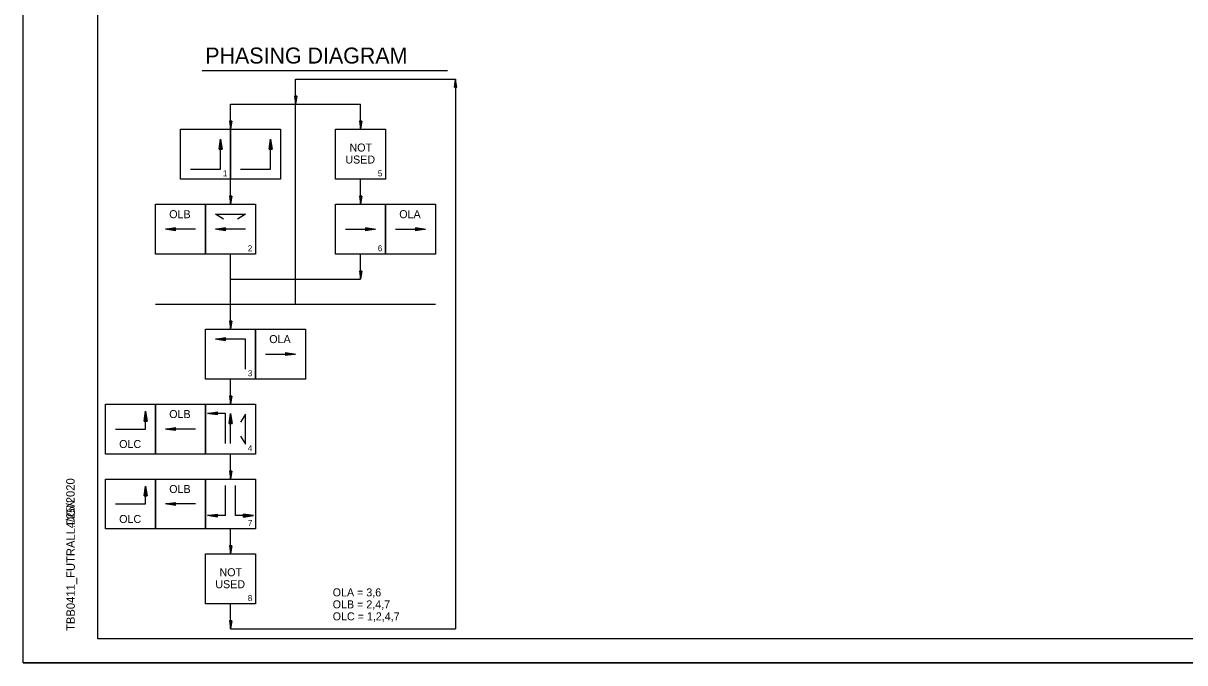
# Model space of a CAD drawing. Extents: x 662183 to 663183, y 642099 to 642739.
# Drawn here: x 662183 to 662763, y 642099 to 642419 of the extents above; entities that cross this region are included whole.
import ezdxf

# ---------------------------------------------------------------- set-up
doc = ezdxf.new("R2010")
doc.units = 0
for name, color, linetype in [('Default', 7, 'Continuous'), ('R_Border', 7, 'Continuous'), ('R_No Plot', 7, 'Continuous'), ('T_Drafting', 7, 'Continuous'), ('T_Notes', 7, 'Continuous')]:
    doc.layers.add(name, color=color, linetype=linetype)

msp = doc.modelspace()

# ---------------------------------------------------------------- linework, layer by layer
at = {"layer": 'Default'}
for p, q in [((662272.06, 642395.65), (662394.71, 642395.65)), ((662398.19, 642387.24), (662398.79, 642391.24)), ((662398.29, 642387.24), (662398.79, 642390.57)), ((662398.39, 642387.24), (662398.79, 642389.89)), ((662398.49, 642387.24), (662398.79, 642389.22)), ((662399.39, 642387.24), (662398.79, 642391.24)), ((662399.29, 642387.24), (662398.79, 642390.57)), ((662399.19, 642387.24), (662398.79, 642389.89)), ((662399.09, 642387.24), (662398.79, 642389.22)), ((662398.19, 642387.24), (662399.39, 642387.24)), ((662398.59, 642387.24), (662398.79, 642388.54)), ((662398.69, 642387.24), (662398.79, 642387.87)), ((662398.98, 642387.24), (662398.79, 642388.54)), ((662398.88, 642387.24), (662398.79, 642387.87)), ((662318.19, 642382.74), (662318.79, 642378.74)), ((662319.39, 642382.74), (662318.19, 642382.74)), ((662318.29, 642382.74), (662318.79, 642379.41)), ((662318.39, 642382.74), (662318.79, 642380.1)), ((662318.49, 642382.74), (662318.79, 642380.76)), ((662318.59, 642382.74), (662318.79, 642381.44)), ((662318.69, 642382.74), (662318.79, 642382.11)), ((662319.39, 642382.74), (662318.79, 642378.74)), ((662318.98, 642382.74), (662318.79, 642381.44)), ((662319.19, 642382.74), (662318.79, 642380.1)), ((662319.29, 642382.74), (662318.79, 642379.41)), ((662319.09, 642382.74), (662318.79, 642380.76)), ((662318.88, 642382.74), (662318.79, 642382.11)), ((662285.69, 642370.24), (662286.29, 642366.24)), ((662286.89, 642370.24), (662285.69, 642370.24)), ((662285.79, 642370.24), (662286.29, 642366.91)), ((662285.89, 642370.24), (662286.29, 642367.6)), ((662285.99, 642370.24), (662286.29, 642368.26)), ((662286.09, 642370.24), (662286.29, 642368.94)), ((662286.19, 642370.24), (662286.29, 642369.61)), ((662286.89, 642370.24), (662286.29, 642366.24)), ((662286.48, 642370.24), (662286.29, 642368.94)), ((662286.69, 642370.24), (662286.29, 642367.6)), ((662286.79, 642370.24), (662286.29, 642366.91)), ((662286.59, 642370.24), (662286.29, 642368.26)), ((662286.38, 642370.24), (662286.29, 642369.61)), ((662350.69, 642370.24), (662351.29, 642366.24)), ((662351.89, 642370.24), (662350.69, 642370.24)), ((662350.79, 642370.24), (662351.29, 642366.91)), ((662350.89, 642370.24), (662351.29, 642367.6)), ((662350.99, 642370.24), (662351.29, 642368.26)), ((662351.09, 642370.24), (662351.29, 642368.94)), ((662351.19, 642370.24), (662351.29, 642369.61)), ((662351.89, 642370.24), (662351.29, 642366.24)), ((662351.48, 642370.24), (662351.29, 642368.94)), ((662351.69, 642370.24), (662351.29, 642367.6)), ((662351.79, 642370.24), (662351.29, 642366.91)), ((662351.59, 642370.24), (662351.29, 642368.26)), ((662351.38, 642370.24), (662351.29, 642369.61)), ((662285.69, 642332.74), (662286.29, 642328.74)), ((662286.89, 642332.74), (662285.69, 642332.74)), ((662285.79, 642332.74), (662286.29, 642329.41)), ((662285.89, 642332.74), (662286.29, 642330.1)), ((662285.99, 642332.74), (662286.29, 642330.76)), ((662286.09, 642332.74), (662286.29, 642331.44)), ((662286.19, 642332.74), (662286.29, 642332.11)), ((662286.89, 642332.74), (662286.29, 642328.74)), ((662286.48, 642332.74), (662286.29, 642331.44)), ((662286.69, 642332.74), (662286.29, 642330.1)), ((662286.79, 642332.74), (662286.29, 642329.41)), ((662286.59, 642332.74), (662286.29, 642330.76)), ((662286.38, 642332.74), (662286.29, 642332.11)), ((662350.69, 642332.74), (662351.29, 642328.74)), ((662351.89, 642332.74), (662350.69, 642332.74)), ((662350.79, 642332.74), (662351.29, 642329.41)), ((662350.89, 642332.74), (662351.29, 642330.1)), ((662350.99, 642332.74), (662351.29, 642330.76)), ((662351.09, 642332.74), (662351.29, 642331.44)), ((662351.19, 642332.74), (662351.29, 642332.11)), ((662351.89, 642332.74), (662351.29, 642328.74)), ((662351.48, 642332.74), (662351.29, 642331.44)), ((662351.69, 642332.74), (662351.29, 642330.1)), ((662351.79, 642332.74), (662351.29, 642329.41)), ((662351.59, 642332.74), (662351.29, 642330.76)), ((662351.38, 642332.74), (662351.29, 642332.11)), ((662350.69, 642295.24), (662351.29, 642291.24)), ((662351.89, 642295.24), (662350.69, 642295.24)), ((662350.79, 642295.24), (662351.29, 642291.91)), ((662350.89, 642295.24), (662351.29, 642292.6)), ((662350.99, 642295.24), (662351.29, 642293.26)), ((662351.09, 642295.24), (662351.29, 642293.94)), ((662351.19, 642295.24), (662351.29, 642294.61)), ((662351.89, 642295.24), (662351.29, 642291.24)), ((662351.48, 642295.24), (662351.29, 642293.94)), ((662351.69, 642295.24), (662351.29, 642292.6)), ((662351.79, 642295.24), (662351.29, 642291.91)), ((662351.59, 642295.24), (662351.29, 642293.26)), ((662351.38, 642295.24), (662351.29, 642294.61)), ((662285.69, 642270.24), (662286.29, 642266.24)), ((662286.89, 642270.24), (662285.69, 642270.24)), ((662285.79, 642270.24), (662286.29, 642266.91)), ((662285.89, 642270.24), (662286.29, 642267.6)), ((662285.99, 642270.24), (662286.29, 642268.26)), ((662286.09, 642270.24), (662286.29, 642268.94)), ((662286.19, 642270.24), (662286.29, 642269.61)), ((662286.89, 642270.24), (662286.29, 642266.24)), ((662286.48, 642270.24), (662286.29, 642268.94)), ((662286.69, 642270.24), (662286.29, 642267.6)), ((662286.79, 642270.24), (662286.29, 642266.91)), ((662286.59, 642270.24), (662286.29, 642268.26)), ((662286.38, 642270.24), (662286.29, 642269.61)), ((662285.69, 642232.74), (662286.29, 642228.74)), ((662286.89, 642232.74), (662285.69, 642232.74)), ((662285.79, 642232.74), (662286.29, 642229.41)), ((662285.89, 642232.74), (662286.29, 642230.1)), ((662285.99, 642232.74), (662286.29, 642230.76)), ((662286.09, 642232.74), (662286.29, 642231.44)), ((662286.19, 642232.74), (662286.29, 642232.11)), ((662286.89, 642232.74), (662286.29, 642228.74)), ((662286.48, 642232.74), (662286.29, 642231.44)), ((662286.69, 642232.74), (662286.29, 642230.1)), ((662286.79, 642232.74), (662286.29, 642229.41)), ((662286.59, 642232.74), (662286.29, 642230.76)), ((662286.38, 642232.74), (662286.29, 642232.11)), ((662285.69, 642195.24), (662286.29, 642191.24)), ((662286.89, 642195.24), (662285.69, 642195.24)), ((662285.79, 642195.24), (662286.29, 642191.91)), ((662285.89, 642195.24), (662286.29, 642192.6)), ((662285.99, 642195.24), (662286.29, 642193.26)), ((662286.09, 642195.24), (662286.29, 642193.94)), ((662286.19, 642195.24), (662286.29, 642194.61)), ((662286.89, 642195.24), (662286.29, 642191.24)), ((662286.48, 642195.24), (662286.29, 642193.94)), ((662286.69, 642195.24), (662286.29, 642192.6)), ((662286.79, 642195.24), (662286.29, 642191.91)), ((662286.59, 642195.24), (662286.29, 642193.26)), ((662286.38, 642195.24), (662286.29, 642194.61)), ((662285.69, 642157.74), (662286.29, 642153.74)), ((662286.89, 642157.74), (662285.69, 642157.74)), ((662285.79, 642157.74), (662286.29, 642154.41)), ((662285.89, 642157.74), (662286.29, 642155.1)), ((662285.99, 642157.74), (662286.29, 642155.76)), ((662286.09, 642157.74), (662286.29, 642156.44)), ((662286.19, 642157.74), (662286.29, 642157.11)), ((662286.89, 642157.74), (662286.29, 642153.74)), ((662286.48, 642157.74), (662286.29, 642156.44)), ((662286.69, 642157.74), (662286.29, 642155.1)), ((662286.79, 642157.74), (662286.29, 642154.41)), ((662286.59, 642157.74), (662286.29, 642155.76)), ((662286.38, 642157.74), (662286.29, 642157.11)), ((662285.69, 642120.24), (662286.29, 642116.24)), ((662286.89, 642120.24), (662285.69, 642120.24)), ((662285.79, 642120.24), (662286.29, 642116.91)), ((662285.89, 642120.24), (662286.29, 642117.6)), ((662285.99, 642120.24), (662286.29, 642118.26)), ((662286.09, 642120.24), (662286.29, 642118.94)), ((662286.19, 642120.24), (662286.29, 642119.61)), ((662286.89, 642120.24), (662286.29, 642116.24)), ((662286.48, 642120.24), (662286.29, 642118.94)), ((662286.69, 642120.24), (662286.29, 642117.6)), ((662286.79, 642120.24), (662286.29, 642116.91)), ((662286.59, 642120.24), (662286.29, 642118.26)), ((662286.38, 642120.24), (662286.29, 642119.61))]:
    msp.add_line(p, q, dxfattribs=at)
at = {"layer": 'R_Border'}
for p, q in [((662219.86, 642111.24), (662219.86, 642727.62)), ((662219.86, 642111.24), (662219.86, 642111.24)), ((663168.4, 642111.24), (662219.86, 642111.24))]:
    msp.add_line(p, q, dxfattribs=at)
at = {"layer": 'R_No Plot'}
msp.add_line((662182.66, 642099.3), (663182.66, 642099.3), dxfattribs=at)
msp.add_lwpolyline([(662182.64, 642739.3), (663182.66, 642739.3), (663182.66, 642099.29), (662182.64, 642099.29)], close=True, dxfattribs=at)
at = {"layer": 'T_Drafting'}
for p, q in [((662318.79, 642278.74), (662318.79, 642391.24)), ((662318.79, 642391.24), (662398.79, 642391.24)), ((662398.79, 642391.24), (662398.79, 642116.24)), ((662286.29, 642366.24), (662286.29, 642378.74)), ((662286.29, 642378.74), (662351.29, 642378.74)), ((662351.29, 642366.24), (662351.29, 642378.74)), ((662280.54, 642356.24), (662281.29, 642361.24)), ((662281.29, 642360.41), (662280.66, 642356.24)), ((662280.79, 642356.24), (662281.29, 642359.55)), ((662281.29, 642346.24), (662281.29, 642361.24)), ((662281.29, 642361.24), (662282.04, 642356.24)), ((662281.91, 642356.24), (662281.29, 642360.41)), ((662281.29, 642359.55), (662281.79, 642356.24)), ((662305.54, 642356.24), (662306.29, 642361.24)), ((662306.29, 642360.41), (662305.66, 642356.24)), ((662305.79, 642356.24), (662306.29, 642359.55)), ((662306.29, 642346.24), (662306.29, 642361.24)), ((662306.29, 642361.24), (662307.04, 642356.24)), ((662306.91, 642356.24), (662306.29, 642360.41)), ((662306.29, 642359.55), (662306.79, 642356.24)), ((662280.54, 642356.24), (662282.04, 642356.24)), ((662281.29, 642358.71), (662280.92, 642356.24)), ((662281.05, 642356.24), (662281.29, 642357.87)), ((662281.29, 642357.03), (662281.17, 642356.24)), ((662281.66, 642356.24), (662281.29, 642358.71)), ((662281.29, 642357.87), (662281.53, 642356.24)), ((662281.41, 642356.24), (662281.29, 642357.03)), ((662305.54, 642356.24), (662307.04, 642356.24)), ((662306.29, 642358.71), (662305.92, 642356.24)), ((662306.05, 642356.24), (662306.29, 642357.87)), ((662306.29, 642357.03), (662306.17, 642356.24)), ((662306.66, 642356.24), (662306.29, 642358.71)), ((662306.29, 642357.87), (662306.53, 642356.24)), ((662306.41, 642356.24), (662306.29, 642357.03)), ((662266.29, 642346.24), (662281.29, 642346.24)), ((662291.29, 642346.24), (662306.29, 642346.24)), ((662286.29, 642328.74), (662286.29, 642341.24)), ((662351.29, 642328.74), (662351.29, 642341.24)), ((662253.79, 642316.24), (662258.79, 642316.99)), ((662268.79, 642316.24), (662253.79, 642316.24)), ((662258.79, 642315.49), (662253.79, 642316.24)), ((662258.79, 642316.87), (662254.62, 642316.24)), ((662254.62, 642316.24), (662258.79, 642315.62)), ((662255.48, 642316.24), (662258.79, 642316.74)), ((662258.79, 642315.74), (662255.48, 642316.24)), ((662258.79, 642316.61), (662256.32, 642316.24)), ((662256.32, 642316.24), (662258.79, 642315.87)), ((662257.16, 642316.24), (662258.79, 642316.49)), ((662258.79, 642316), (662257.16, 642316.24)), ((662258.79, 642316.36), (662258, 642316.24)), ((662258, 642316.24), (662258.79, 642316.12)), ((662258.79, 642315.49), (662258.79, 642316.99)), ((662278.79, 642316.24), (662283.79, 642316.99)), ((662293.79, 642316.24), (662278.79, 642316.24)), ((662283.79, 642315.49), (662278.79, 642316.24)), ((662283.79, 642316.87), (662279.62, 642316.24)), ((662279.62, 642316.24), (662283.79, 642315.62)), ((662280.48, 642316.24), (662283.79, 642316.74)), ((662283.79, 642315.74), (662280.48, 642316.24)), ((662283.79, 642316.61), (662281.32, 642316.24)), ((662281.32, 642316.24), (662283.79, 642315.87)), ((662282.16, 642316.24), (662283.79, 642316.49)), ((662283.79, 642316), (662282.16, 642316.24)), ((662283.79, 642316.36), (662283, 642316.24)), ((662283, 642316.24), (662283.79, 642316.12)), ((662283.79, 642315.49), (662283.79, 642316.99)), ((662343.79, 642316.24), (662358.79, 642316.24)), ((662353.79, 642316.99), (662358.79, 642316.24)), ((662353.79, 642316.99), (662353.79, 642315.49)), ((662357.95, 642316.24), (662353.79, 642316.87)), ((662353.79, 642316.74), (662357.09, 642316.24)), ((662356.26, 642316.24), (662353.79, 642316.61)), ((662353.79, 642316.48), (662355.41, 642316.24)), ((662354.58, 642316.24), (662353.79, 642316.36)), ((662358.79, 642316.24), (662353.79, 642315.49)), ((662353.79, 642315.62), (662357.95, 642316.24)), ((662357.09, 642316.24), (662353.79, 642315.74)), ((662353.79, 642315.87), (662356.26, 642316.24)), ((662355.41, 642316.24), (662353.79, 642316)), ((662353.79, 642316.12), (662354.58, 642316.24)), ((662368.79, 642316.24), (662383.79, 642316.24)), ((662378.79, 642316.99), (662383.79, 642316.24)), ((662378.79, 642316.99), (662378.79, 642315.49)), ((662382.95, 642316.24), (662378.79, 642316.87)), ((662378.79, 642316.74), (662382.09, 642316.24)), ((662381.26, 642316.24), (662378.79, 642316.61)), ((662378.79, 642316.48), (662380.41, 642316.24)), ((662379.58, 642316.24), (662378.79, 642316.36)), ((662383.79, 642316.24), (662378.79, 642315.49)), ((662378.79, 642315.62), (662382.95, 642316.24)), ((662382.09, 642316.24), (662378.79, 642315.74)), ((662378.79, 642315.87), (662381.26, 642316.24)), ((662380.41, 642316.24), (662378.79, 642316)), ((662378.79, 642316.12), (662379.58, 642316.24)), ((662286.29, 642266.24), (662286.29, 642303.74)), ((662351.29, 642291.24), (662351.29, 642303.74)), ((662286.29, 642291.24), (662351.29, 642291.24)), ((662248.79, 642278.74), (662388.79, 642278.74)), ((662278.79, 642261.24), (662283.79, 642261.99)), ((662293.79, 642261.24), (662278.79, 642261.24)), ((662283.79, 642260.49), (662278.79, 642261.24)), ((662283.79, 642261.87), (662279.62, 642261.24)), ((662279.62, 642261.24), (662283.79, 642260.62)), ((662280.48, 642261.24), (662283.79, 642261.74)), ((662283.79, 642260.74), (662280.48, 642261.24)), ((662283.79, 642261.61), (662281.32, 642261.24)), ((662281.32, 642261.24), (662283.79, 642260.87)), ((662282.16, 642261.24), (662283.79, 642261.49)), ((662283.79, 642261), (662282.16, 642261.24)), ((662283.79, 642261.36), (662283, 642261.24)), ((662283, 642261.24), (662283.79, 642261.12)), ((662283.79, 642260.49), (662283.79, 642261.99)), ((662293.79, 642246.24), (662293.79, 642261.24)), ((662303.79, 642253.74), (662318.79, 642253.74)), ((662313.79, 642254.49), (662318.79, 642253.74)), ((662313.79, 642254.49), (662313.79, 642252.99)), ((662317.95, 642253.74), (662313.79, 642254.37)), ((662313.79, 642254.24), (662317.09, 642253.74)), ((662316.26, 642253.74), (662313.79, 642254.11)), ((662313.79, 642253.98), (662315.41, 642253.74)), ((662314.58, 642253.74), (662313.79, 642253.86)), ((662318.79, 642253.74), (662313.79, 642252.99)), ((662313.79, 642253.12), (662317.95, 642253.74)), ((662317.09, 642253.74), (662313.79, 642253.24)), ((662313.79, 642253.37), (662316.26, 642253.74)), ((662315.41, 642253.74), (662313.79, 642253.5)), ((662313.79, 642253.62), (662314.58, 642253.74)), ((662286.29, 642228.74), (662286.29, 642241.24)), ((662243.04, 642220.24), (662243.79, 642225.24)), ((662243.04, 642220.24), (662244.54, 642220.24)), ((662243.79, 642224.41), (662243.16, 642220.24)), ((662243.29, 642220.24), (662243.79, 642223.55)), ((662243.79, 642222.71), (662243.42, 642220.24)), ((662243.55, 642220.24), (662243.79, 642221.87)), ((662243.79, 642221.03), (662243.67, 642220.24)), ((662243.79, 642216.24), (662243.79, 642225.24)), ((662243.79, 642225.24), (662244.54, 642220.24)), ((662244.41, 642220.24), (662243.79, 642224.41)), ((662243.79, 642223.55), (662244.29, 642220.24)), ((662244.16, 642220.24), (662243.79, 642222.71)), ((662243.79, 642221.87), (662244.03, 642220.24)), ((662243.91, 642220.24), (662243.79, 642221.03)), ((662274.79, 642224.08), (662279.79, 642224.83)), ((662283.79, 642224.08), (662274.79, 642224.08)), ((662279.79, 642223.33), (662274.79, 642224.08)), ((662279.79, 642224.7), (662275.62, 642224.08)), ((662275.62, 642224.08), (662279.79, 642223.45)), ((662276.48, 642224.08), (662279.79, 642224.57)), ((662279.79, 642223.58), (662276.48, 642224.08)), ((662279.79, 642224.45), (662277.32, 642224.08)), ((662277.32, 642224.08), (662279.79, 642223.7)), ((662278.16, 642224.08), (662279.79, 642224.32)), ((662279.79, 642223.83), (662278.16, 642224.08)), ((662279.79, 642224.19), (662279, 642224.08)), ((662279, 642224.08), (662279.79, 642223.96)), ((662279.79, 642223.33), (662279.79, 642224.83)), ((662283.79, 642209.08), (662283.79, 642224.08)), ((662285.54, 642219.08), (662286.29, 642224.08)), ((662286.29, 642223.24), (662285.66, 642219.08)), ((662285.79, 642219.08), (662286.29, 642222.38)), ((662286.29, 642221.55), (662285.92, 642219.08)), ((662286.05, 642219.08), (662286.29, 642220.7)), ((662286.29, 642209.08), (662286.29, 642224.08)), ((662286.29, 642224.08), (662287.04, 642219.08)), ((662286.91, 642219.08), (662286.29, 642223.24)), ((662286.29, 642222.38), (662286.79, 642219.08)), ((662286.66, 642219.08), (662286.29, 642221.55)), ((662286.29, 642220.7), (662286.53, 642219.08)), ((662228.79, 642216.24), (662243.79, 642216.24)), ((662253.79, 642216.24), (662258.79, 642216.99)), ((662268.79, 642216.24), (662253.79, 642216.24)), ((662258.79, 642215.49), (662253.79, 642216.24)), ((662258.79, 642216.87), (662254.62, 642216.24)), ((662254.62, 642216.24), (662258.79, 642215.62)), ((662255.48, 642216.24), (662258.79, 642216.74)), ((662258.79, 642215.74), (662255.48, 642216.24)), ((662258.79, 642216.61), (662256.32, 642216.24)), ((662256.32, 642216.24), (662258.79, 642215.87)), ((662257.16, 642216.24), (662258.79, 642216.49)), ((662258.79, 642216), (662257.16, 642216.24)), ((662258.79, 642216.36), (662258, 642216.24)), ((662258, 642216.24), (662258.79, 642216.12)), ((662258.79, 642215.49), (662258.79, 642216.99)), ((662285.54, 642219.08), (662287.04, 642219.08)), ((662286.29, 642219.87), (662286.17, 642219.08)), ((662286.41, 642219.08), (662286.29, 642219.87)), ((662286.29, 642191.24), (662286.29, 642203.74)), ((662243.04, 642182.74), (662243.79, 642187.74)), ((662243.79, 642186.91), (662243.16, 642182.74)), ((662243.29, 642182.74), (662243.79, 642186.05)), ((662243.79, 642178.74), (662243.79, 642187.74)), ((662243.79, 642187.74), (662244.54, 642182.74)), ((662244.41, 642182.74), (662243.79, 642186.91)), ((662243.79, 642186.05), (662244.29, 642182.74)), ((662283.79, 642172.91), (662283.79, 642187.91)), ((662288.79, 642172.91), (662288.79, 642187.91)), ((662243.04, 642182.74), (662244.54, 642182.74)), ((662243.79, 642185.21), (662243.42, 642182.74)), ((662243.55, 642182.74), (662243.79, 642184.37)), ((662243.79, 642183.53), (662243.67, 642182.74)), ((662244.16, 642182.74), (662243.79, 642185.21)), ((662243.79, 642184.37), (662244.03, 642182.74)), ((662243.91, 642182.74), (662243.79, 642183.53)), ((662253.79, 642178.74), (662258.79, 642179.49)), ((662258.79, 642177.99), (662258.79, 642179.49)), ((662228.79, 642178.74), (662243.79, 642178.74)), ((662268.79, 642178.74), (662253.79, 642178.74)), ((662258.79, 642177.99), (662253.79, 642178.74)), ((662258.79, 642179.37), (662254.62, 642178.74)), ((662254.62, 642178.74), (662258.79, 642178.12)), ((662255.48, 642178.74), (662258.79, 642179.24)), ((662258.79, 642178.24), (662255.48, 642178.74)), ((662258.79, 642179.11), (662256.32, 642178.74)), ((662256.32, 642178.74), (662258.79, 642178.37)), ((662257.16, 642178.74), (662258.79, 642178.99)), ((662258.79, 642178.5), (662257.16, 642178.74)), ((662258.79, 642178.86), (662258, 642178.74)), ((662258, 642178.74), (662258.79, 642178.62)), ((662274.79, 642172.91), (662279.79, 642173.66)), ((662283.79, 642172.91), (662274.79, 642172.91)), ((662279.79, 642172.16), (662274.79, 642172.91)), ((662279.79, 642173.54), (662275.62, 642172.91)), ((662275.62, 642172.91), (662279.79, 642172.29)), ((662276.48, 642172.91), (662279.79, 642173.41)), ((662279.79, 642172.41), (662276.48, 642172.91)), ((662279.79, 642173.28), (662277.32, 642172.91)), ((662277.32, 642172.91), (662279.79, 642172.54)), ((662278.16, 642172.91), (662279.79, 642173.16)), ((662279.79, 642172.67), (662278.16, 642172.91)), ((662279.79, 642173.03), (662279, 642172.91)), ((662279, 642172.91), (662279.79, 642172.79)), ((662279.79, 642172.16), (662279.79, 642173.66)), ((662297.79, 642172.91), (662288.79, 642172.91)), ((662297.79, 642172.91), (662292.79, 642173.66)), ((662292.79, 642172.16), (662292.79, 642173.66)), ((662292.79, 642173.54), (662296.95, 642172.91)), ((662296.09, 642172.91), (662292.79, 642173.41)), ((662292.79, 642173.28), (662295.26, 642172.91)), ((662294.41, 642172.91), (662292.79, 642173.16)), ((662292.79, 642173.03), (662293.58, 642172.91)), ((662293.58, 642172.91), (662292.79, 642172.79)), ((662292.79, 642172.67), (662294.41, 642172.91)), ((662295.26, 642172.91), (662292.79, 642172.54)), ((662292.79, 642172.41), (662296.09, 642172.91)), ((662296.95, 642172.91), (662292.79, 642172.29)), ((662292.79, 642172.16), (662297.79, 642172.91)), ((662286.29, 642153.74), (662286.29, 642166.24)), ((662286.29, 642116.24), (662286.29, 642128.74)), ((662286.29, 642116.24), (662398.79, 642116.24))]:
    msp.add_line(p, q, dxfattribs=at)
for points in [[(662261.29, 642366.24), (662286.29, 642366.24), (662286.29, 642341.24), (662261.29, 642341.24)], [(662286.29, 642366.24), (662311.29, 642366.24), (662311.29, 642341.24), (662286.29, 642341.24)], [(662338.79, 642366.24), (662363.79, 642366.24), (662363.79, 642341.24), (662338.79, 642341.24)], [(662248.79, 642328.74), (662273.79, 642328.74), (662273.79, 642303.74), (662248.79, 642303.74)], [(662273.79, 642328.74), (662298.79, 642328.74), (662298.79, 642303.74), (662273.79, 642303.74)], [(662338.79, 642328.74), (662363.79, 642328.74), (662363.79, 642303.74), (662338.79, 642303.74)], [(662363.79, 642328.74), (662388.79, 642328.74), (662388.79, 642303.74), (662363.79, 642303.74)], [(662273.79, 642266.24), (662298.79, 642266.24), (662298.79, 642241.24), (662273.79, 642241.24)], [(662298.79, 642266.24), (662323.79, 642266.24), (662323.79, 642241.24), (662298.79, 642241.24)], [(662223.79, 642228.74), (662248.79, 642228.74), (662248.79, 642203.74), (662223.79, 642203.74)], [(662248.79, 642228.74), (662273.79, 642228.74), (662273.79, 642203.74), (662248.79, 642203.74)], [(662273.79, 642228.74), (662298.79, 642228.74), (662298.79, 642203.74), (662273.79, 642203.74)], [(662223.79, 642191.24), (662248.79, 642191.24), (662248.79, 642166.24), (662223.79, 642166.24)], [(662248.79, 642191.24), (662273.79, 642191.24), (662273.79, 642166.24), (662248.79, 642166.24)], [(662273.79, 642191.24), (662298.79, 642191.24), (662298.79, 642166.24), (662273.79, 642166.24)], [(662273.79, 642153.74), (662298.79, 642153.74), (662298.79, 642128.74), (662273.79, 642128.74)]]:
    msp.add_lwpolyline(points, close=True, dxfattribs=at)
for points in [[(662282.79, 642321.24), (662278.79, 642323.74), (662293.79, 642323.74), (662289.79, 642321.24)], [(662291.29, 642212.74), (662293.79, 642208.74), (662293.79, 642223.74), (662291.29, 642219.74)]]:
    msp.add_lwpolyline(points, dxfattribs=at)

# ---------------------------------------------------------------- texts
at = {"layer": 'Default'}
for s, height, p in [('PHASING DIAGRAM', 8, (662273.66, 642399.12)), ('1', 3, (662282.44, 642342.66)), ('2', 3, (662294.94, 642305.16)), ('6', 3, (662359.94, 642305.16)), ('3', 3, (662294.94, 642242.66)), ('4', 3, (662294.94, 642205.16)), ('7', 3, (662294.94, 642167.66))]:
    msp.add_text(s, height=height, dxfattribs=at).set_placement(p)
at = {"layer": 'R_Border'}
for s, p in [('4/25/2020', (662208.34, 642166.63)), ('TBB0411_FUTRALL.DGN', (662208.44, 642115.21))]:
    msp.add_text(s, height=4.2, rotation=90, dxfattribs=at).set_placement(p)
at = {"layer": 'T_Drafting'}
for s, height, p in [('NOT', 4, (662345.76, 642355.09)), ('USED', 4, (662343.69, 642349.09)), ('5', 3, (662359.94, 642342.66)), ('OLB', 4, (662255.63, 642321.74)), ('OLA', 4, (662370.65, 642321.74)), ('OLA', 4, (662305.65, 642259.24)), ('OLB', 4, (662255.63, 642221.74)), ('OLC', 4, (662230.62, 642206.74)), ('OLB', 4, (662255.63, 642184.24)), ('OLC', 4, (662230.62, 642169.24)), ('NOT', 4, (662280.76, 642142.59)), ('USED', 4, (662278.69, 642136.59)), ('OLA = 3,6', 4, (662337.37, 642132.51)), ('OLB = 2,4,7', 4, (662337.37, 642126.51)), ('OLC = 1,2,4,7', 4, (662337.37, 642120.51))]:
    msp.add_text(s, height=height, dxfattribs=at).set_placement(p)
at = {"layer": 'T_Notes'}
msp.add_text('8', height=3, dxfattribs=at).set_placement((662294.94, 642130.16))

doc.saveas('drawing.dxf')
